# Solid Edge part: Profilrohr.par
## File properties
Username: bmolnar
Dokumentum tartalom típus: 0
Author: bmolnar
Last saved by: bmolnar
Revision: 79
Sűrűség: 0,000 kg/m^3
Pontosság: 0,990
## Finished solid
Body 1: solid body, 115 faces, 338 edges, 224 vertices.
  Faces by surface: cylinder 59, plane 56
  Edges by curve: line 220, circle 118
Bounding box of the edges (mm): 113.500 x 113.500 x 48.000, from (-56.75, -56.75, -31.5) to (56.75, 56.75, 16.5).
Cylindrical faces by radius (mm): R0.15 x24, R0.25 x24, R1 x4, R12.25 x4, R35 x2, R50 x1
Planar faces by outward normal: +x 13, +y 14, +z 1, -x 13, -y 14, -z 1
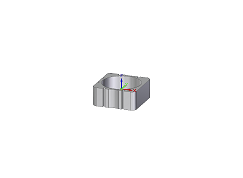
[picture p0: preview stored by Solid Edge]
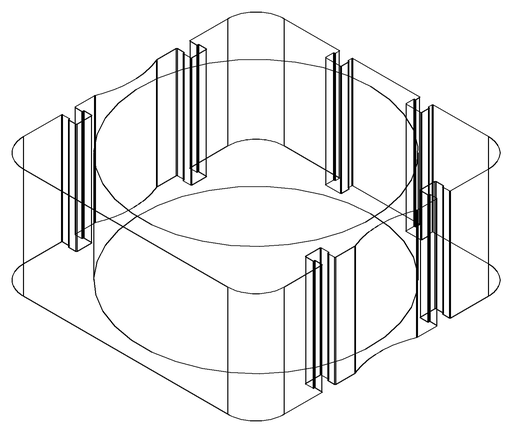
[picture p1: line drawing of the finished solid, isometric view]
